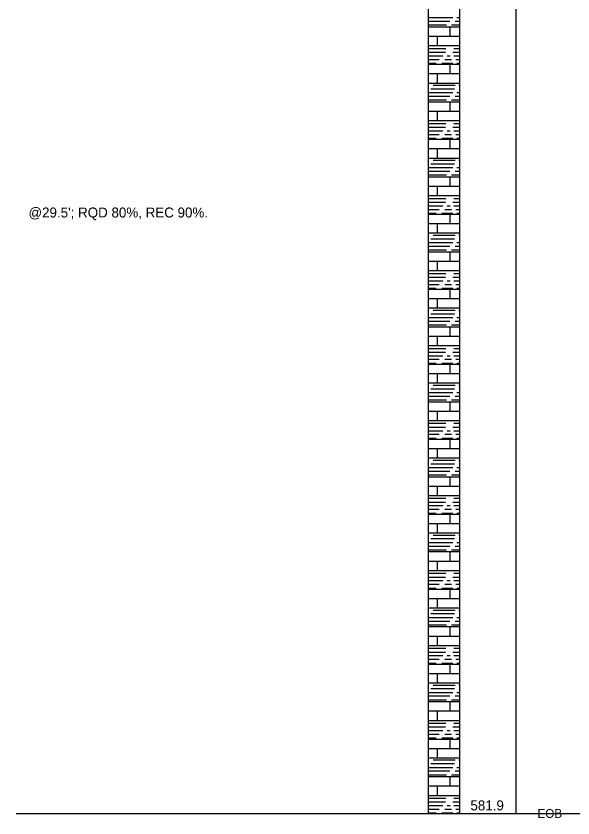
# Model space of a CAD drawing. Extents: x -0.01 to 0.83, y -0.63 to 1.27.
# Drawn here: x 0 to 0.372, y -0.625 to -0.09 of the extents above; entities that cross this region are included whole.
import ezdxf

# ---------------------------------------------------------------- set-up
doc = ezdxf.new("R2010")
doc.units = 0

msp = doc.modelspace()

# ---------------------------------------------------------------- linework, layer by layer
for points in [[(0.29583, 1.22083), (0.29583, -0.62183)], [(0.29583, 1.22083), (0.29583, -0.62183)], [(0.33333, 1.22083), (0.33333, -0.62183)], [(0.33333, 1.22083), (0.33333, -0.62183)], [(0.275, 1.19583), (0.275, -0.62183)], [(0.275, 0.21525), (0.275, -0.62183)], [(0.275, -0.09108), (0.29133, -0.09108)], [(0.275, -0.0935), (0.28933, -0.0935)], [(0.275, -0.096), (0.28725, -0.096)], [(0.2905, -0.096), (0.29583, -0.096)], [(0.293, -0.0935), (0.29583, -0.0935)], [(0.29417, -0.09108), (0.29583, -0.09108)], [(0.275, -0.09725), (0.29583, -0.09725)], [(0.28958, -0.1035), (0.28958, -0.09725)], [(0.275, -0.1035), (0.29583, -0.1035)], [(0.28125, -0.10975), (0.28125, -0.1035)], [(0.275, -0.10975), (0.29583, -0.10975)], [(0.275, -0.11167), (0.28683, -0.11167)], [(0.29217, -0.11167), (0.29583, -0.11167)], [(0.275, -0.11417), (0.28642, -0.11417)], [(0.275, -0.11658), (0.28483, -0.11658)], [(0.28767, -0.11658), (0.28967, -0.11658)], [(0.29133, -0.11417), (0.29583, -0.11417)], [(0.29217, -0.11658), (0.29583, -0.11658)], [(0.275, -0.119), (0.28233, -0.119)], [(0.275, -0.1215), (0.28033, -0.1215)], [(0.275, -0.12225), (0.29583, -0.12225)], [(0.284, -0.1215), (0.29133, -0.1215)], [(0.286, -0.119), (0.2905, -0.119)], [(0.28958, -0.1285), (0.28958, -0.12225)], [(0.29342, -0.119), (0.29583, -0.119)], [(0.29417, -0.1215), (0.29583, -0.1215)], [(0.275, -0.1285), (0.29583, -0.1285)], [(0.28125, -0.13475), (0.28125, -0.1285)], [(0.275, -0.13475), (0.29583, -0.13475)], [(0.27667, -0.13858), (0.29258, -0.13858)], [(0.27825, -0.13617), (0.293, -0.13617)], [(0.29542, -0.13617), (0.29583, -0.13617)], [(0.275, -0.14108), (0.29133, -0.14108)], [(0.275, -0.1435), (0.28933, -0.1435)], [(0.293, -0.1435), (0.29583, -0.1435)], [(0.29417, -0.14108), (0.29583, -0.14108)], [(0.275, -0.146), (0.28725, -0.146)], [(0.275, -0.14725), (0.29583, -0.14725)], [(0.28958, -0.1535), (0.28958, -0.14725)], [(0.2905, -0.146), (0.29583, -0.146)], [(0.275, -0.1535), (0.29583, -0.1535)], [(0.28125, -0.15975), (0.28125, -0.1535)], [(0.275, -0.15975), (0.29583, -0.15975)], [(0.275, -0.16167), (0.28683, -0.16167)], [(0.275, -0.16417), (0.28642, -0.16417)], [(0.29133, -0.16417), (0.29583, -0.16417)], [(0.29217, -0.16167), (0.29583, -0.16167)], [(0.275, -0.16658), (0.28483, -0.16658)], [(0.275, -0.169), (0.28233, -0.169)], [(0.286, -0.169), (0.2905, -0.169)], [(0.28767, -0.16658), (0.28967, -0.16658)], [(0.29217, -0.16658), (0.29583, -0.16658)], [(0.29342, -0.169), (0.29583, -0.169)], [(0.275, -0.1715), (0.28033, -0.1715)], [(0.275, -0.17225), (0.29583, -0.17225)], [(0.284, -0.1715), (0.29133, -0.1715)], [(0.28958, -0.1785), (0.28958, -0.17225)], [(0.29417, -0.1715), (0.29583, -0.1715)], [(0.275, -0.1785), (0.29583, -0.1785)], [(0.28125, -0.18475), (0.28125, -0.1785)], [(0.275, -0.18475), (0.29583, -0.18475)], [(0.27825, -0.18617), (0.293, -0.18617)], [(0.29542, -0.18617), (0.29583, -0.18617)], [(0.275, -0.19108), (0.29133, -0.19108)], [(0.27667, -0.18858), (0.29258, -0.18858)], [(0.29417, -0.19108), (0.29583, -0.19108)], [(0.275, -0.1935), (0.28933, -0.1935)], [(0.275, -0.196), (0.28725, -0.196)], [(0.275, -0.19725), (0.29583, -0.19725)], [(0.28958, -0.2035), (0.28958, -0.19725)], [(0.2905, -0.196), (0.29583, -0.196)], [(0.293, -0.1935), (0.29583, -0.1935)], [(0.275, -0.2035), (0.29583, -0.2035)], [(0.28125, -0.20975), (0.28125, -0.2035)], [(0.275, -0.20975), (0.29583, -0.20975)], [(0.275, -0.21167), (0.28683, -0.21167)], [(0.29217, -0.21167), (0.29583, -0.21167)], [(0.275, -0.21417), (0.28642, -0.21417)], [(0.275, -0.21658), (0.28483, -0.21658)], [(0.275, -0.219), (0.28233, -0.219)], [(0.286, -0.219), (0.2905, -0.219)], [(0.28767, -0.21658), (0.28967, -0.21658)], [(0.29133, -0.21417), (0.29583, -0.21417)], [(0.29217, -0.21658), (0.29583, -0.21658)], [(0.29342, -0.219), (0.29583, -0.219)], [(0.275, -0.2215), (0.28033, -0.2215)], [(0.275, -0.22225), (0.29583, -0.22225)], [(0.284, -0.2215), (0.29133, -0.2215)], [(0.28958, -0.2285), (0.28958, -0.22225)], [(0.29417, -0.2215), (0.29583, -0.2215)], [(0.275, -0.2285), (0.29583, -0.2285)], [(0.28125, -0.23475), (0.28125, -0.2285)], [(0.275, -0.23475), (0.29583, -0.23475)], [(0.27667, -0.23858), (0.29258, -0.23858)], [(0.27825, -0.23617), (0.293, -0.23617)], [(0.29542, -0.23617), (0.29583, -0.23617)], [(0.275, -0.24108), (0.29133, -0.24108)], [(0.275, -0.2435), (0.28933, -0.2435)], [(0.293, -0.2435), (0.29583, -0.2435)], [(0.29417, -0.24108), (0.29583, -0.24108)], [(0.275, -0.246), (0.28725, -0.246)], [(0.275, -0.24725), (0.29583, -0.24725)], [(0.28958, -0.2535), (0.28958, -0.24725)], [(0.2905, -0.246), (0.29583, -0.246)], [(0.275, -0.2535), (0.29583, -0.2535)], [(0.28125, -0.25975), (0.28125, -0.2535)], [(0.275, -0.25975), (0.29583, -0.25975)], [(0.275, -0.26167), (0.28683, -0.26167)], [(0.29217, -0.26167), (0.29583, -0.26167)], [(0.275, -0.26417), (0.28642, -0.26417)], [(0.275, -0.26658), (0.28483, -0.26658)], [(0.28767, -0.26658), (0.28967, -0.26658)], [(0.29133, -0.26417), (0.29583, -0.26417)], [(0.29217, -0.26658), (0.29583, -0.26658)], [(0.275, -0.269), (0.28233, -0.269)], [(0.275, -0.2715), (0.28033, -0.2715)], [(0.275, -0.27225), (0.29583, -0.27225)], [(0.284, -0.2715), (0.29133, -0.2715)], [(0.286, -0.269), (0.2905, -0.269)], [(0.28958, -0.2785), (0.28958, -0.27225)], [(0.29342, -0.269), (0.29583, -0.269)], [(0.29417, -0.2715), (0.29583, -0.2715)], [(0.275, -0.2785), (0.29583, -0.2785)], [(0.28125, -0.28475), (0.28125, -0.2785)], [(0.275, -0.28475), (0.29583, -0.28475)], [(0.27667, -0.28858), (0.29258, -0.28858)], [(0.27825, -0.28617), (0.293, -0.28617)], [(0.29542, -0.28617), (0.29583, -0.28617)], [(0.275, -0.29108), (0.29133, -0.29108)], [(0.275, -0.2935), (0.28933, -0.2935)], [(0.293, -0.2935), (0.29583, -0.2935)], [(0.29417, -0.29108), (0.29583, -0.29108)], [(0.275, -0.296), (0.28725, -0.296)], [(0.275, -0.29725), (0.29583, -0.29725)], [(0.28958, -0.3035), (0.28958, -0.29725)], [(0.2905, -0.296), (0.29583, -0.296)], [(0.275, -0.3035), (0.29583, -0.3035)], [(0.28125, -0.30975), (0.28125, -0.3035)], [(0.275, -0.30975), (0.29583, -0.30975)], [(0.275, -0.31167), (0.28683, -0.31167)], [(0.275, -0.31417), (0.28642, -0.31417)], [(0.29133, -0.31417), (0.29583, -0.31417)], [(0.29217, -0.31167), (0.29583, -0.31167)], [(0.275, -0.31658), (0.28483, -0.31658)], [(0.275, -0.319), (0.28233, -0.319)], [(0.286, -0.319), (0.2905, -0.319)], [(0.28767, -0.31658), (0.28967, -0.31658)], [(0.29217, -0.31658), (0.29583, -0.31658)], [(0.29342, -0.319), (0.29583, -0.319)], [(0.275, -0.3215), (0.28033, -0.3215)], [(0.275, -0.32225), (0.29583, -0.32225)], [(0.284, -0.3215), (0.29133, -0.3215)], [(0.28958, -0.3285), (0.28958, -0.32225)], [(0.29417, -0.3215), (0.29583, -0.3215)], [(0.275, -0.3285), (0.29583, -0.3285)], [(0.28125, -0.33475), (0.28125, -0.3285)], [(0.275, -0.33475), (0.29583, -0.33475)], [(0.27825, -0.33617), (0.293, -0.33617)], [(0.29542, -0.33617), (0.29583, -0.33617)], [(0.275, -0.34108), (0.29133, -0.34108)], [(0.27667, -0.33858), (0.29258, -0.33858)], [(0.29417, -0.34108), (0.29583, -0.34108)], [(0.275, -0.3435), (0.28933, -0.3435)], [(0.275, -0.346), (0.28725, -0.346)], [(0.275, -0.34725), (0.29583, -0.34725)], [(0.28958, -0.3535), (0.28958, -0.34725)], [(0.2905, -0.346), (0.29583, -0.346)], [(0.293, -0.3435), (0.29583, -0.3435)], [(0.275, -0.3535), (0.29583, -0.3535)], [(0.28125, -0.35975), (0.28125, -0.3535)], [(0.275, -0.35975), (0.29583, -0.35975)], [(0.275, -0.36167), (0.28683, -0.36167)], [(0.29217, -0.36167), (0.29583, -0.36167)], [(0.275, -0.36417), (0.28642, -0.36417)], [(0.275, -0.36658), (0.28483, -0.36658)], [(0.28767, -0.36658), (0.28967, -0.36658)], [(0.29133, -0.36417), (0.29583, -0.36417)], [(0.29217, -0.36658), (0.29583, -0.36658)], [(0.275, -0.369), (0.28233, -0.369)], [(0.275, -0.3715), (0.28033, -0.3715)], [(0.275, -0.37225), (0.29583, -0.37225)], [(0.284, -0.3715), (0.29133, -0.3715)], [(0.286, -0.369), (0.2905, -0.369)], [(0.28958, -0.3785), (0.28958, -0.37225)], [(0.29342, -0.369), (0.29583, -0.369)], [(0.29417, -0.3715), (0.29583, -0.3715)], [(0.275, -0.3785), (0.29583, -0.3785)], [(0.28125, -0.38475), (0.28125, -0.3785)], [(0.275, -0.38475), (0.29583, -0.38475)], [(0.27667, -0.38858), (0.29258, -0.38858)], [(0.27825, -0.38617), (0.293, -0.38617)], [(0.29542, -0.38617), (0.29583, -0.38617)], [(0.275, -0.39108), (0.29133, -0.39108)], [(0.275, -0.3935), (0.28933, -0.3935)], [(0.293, -0.3935), (0.29583, -0.3935)], [(0.29417, -0.39108), (0.29583, -0.39108)], [(0.275, -0.396), (0.28725, -0.396)], [(0.275, -0.39725), (0.29583, -0.39725)], [(0.28958, -0.4035), (0.28958, -0.39725)], [(0.2905, -0.396), (0.29583, -0.396)], [(0.275, -0.4035), (0.29583, -0.4035)], [(0.28125, -0.40975), (0.28125, -0.4035)], [(0.275, -0.40975), (0.29583, -0.40975)], [(0.275, -0.41167), (0.28683, -0.41167)], [(0.29217, -0.41167), (0.29583, -0.41167)], [(0.275, -0.41417), (0.28642, -0.41417)], [(0.275, -0.41658), (0.28483, -0.41658)], [(0.28767, -0.41658), (0.28967, -0.41658)], [(0.29133, -0.41417), (0.29583, -0.41417)], [(0.29217, -0.41658), (0.29583, -0.41658)], [(0.275, -0.419), (0.28233, -0.419)], [(0.275, -0.4215), (0.28033, -0.4215)], [(0.275, -0.42225), (0.29583, -0.42225)], [(0.284, -0.4215), (0.29133, -0.4215)], [(0.286, -0.419), (0.2905, -0.419)], [(0.28958, -0.4285), (0.28958, -0.42225)], [(0.29342, -0.419), (0.29583, -0.419)], [(0.29417, -0.4215), (0.29583, -0.4215)], [(0.275, -0.4285), (0.29583, -0.4285)], [(0.28125, -0.43475), (0.28125, -0.4285)], [(0.275, -0.43475), (0.29583, -0.43475)], [(0.27825, -0.43617), (0.293, -0.43617)], [(0.29542, -0.43617), (0.29583, -0.43617)], [(0.275, -0.44108), (0.29133, -0.44108)], [(0.275, -0.4435), (0.28933, -0.4435)], [(0.27667, -0.43858), (0.29258, -0.43858)], [(0.293, -0.4435), (0.29583, -0.4435)], [(0.29417, -0.44108), (0.29583, -0.44108)], [(0.275, -0.446), (0.28725, -0.446)], [(0.275, -0.44725), (0.29583, -0.44725)], [(0.28958, -0.4535), (0.28958, -0.44725)], [(0.2905, -0.446), (0.29583, -0.446)], [(0.275, -0.4535), (0.29583, -0.4535)], [(0.28125, -0.45975), (0.28125, -0.4535)], [(0.275, -0.45975), (0.29583, -0.45975)], [(0.275, -0.46167), (0.28683, -0.46167)], [(0.275, -0.46417), (0.28642, -0.46417)], [(0.29133, -0.46417), (0.29583, -0.46417)], [(0.29217, -0.46167), (0.29583, -0.46167)], [(0.275, -0.46658), (0.28483, -0.46658)], [(0.275, -0.469), (0.28233, -0.469)], [(0.286, -0.469), (0.2905, -0.469)], [(0.28767, -0.46658), (0.28967, -0.46658)], [(0.29217, -0.46658), (0.29583, -0.46658)], [(0.29342, -0.469), (0.29583, -0.469)], [(0.275, -0.4715), (0.28033, -0.4715)], [(0.275, -0.47225), (0.29583, -0.47225)], [(0.284, -0.4715), (0.29133, -0.4715)], [(0.28958, -0.4785), (0.28958, -0.47225)], [(0.29417, -0.4715), (0.29583, -0.4715)], [(0.275, -0.4785), (0.29583, -0.4785)], [(0.28125, -0.48475), (0.28125, -0.4785)], [(0.275, -0.48475), (0.29583, -0.48475)], [(0.27825, -0.48617), (0.293, -0.48617)], [(0.29542, -0.48617), (0.29583, -0.48617)], [(0.275, -0.49108), (0.29133, -0.49108)], [(0.27667, -0.48858), (0.29258, -0.48858)], [(0.29417, -0.49108), (0.29583, -0.49108)], [(0.275, -0.4935), (0.28933, -0.4935)], [(0.275, -0.496), (0.28725, -0.496)], [(0.275, -0.49725), (0.29583, -0.49725)], [(0.28958, -0.5035), (0.28958, -0.49725)], [(0.2905, -0.496), (0.29583, -0.496)], [(0.293, -0.4935), (0.29583, -0.4935)], [(0.275, -0.5035), (0.29583, -0.5035)], [(0.28125, -0.50975), (0.28125, -0.5035)], [(0.275, -0.50975), (0.29583, -0.50975)], [(0.275, -0.51167), (0.28683, -0.51167)], [(0.29217, -0.51167), (0.29583, -0.51167)], [(0.275, -0.51417), (0.28642, -0.51417)], [(0.275, -0.51658), (0.28483, -0.51658)], [(0.28767, -0.51658), (0.28967, -0.51658)], [(0.29133, -0.51417), (0.29583, -0.51417)], [(0.29217, -0.51658), (0.29583, -0.51658)], [(0.275, -0.519), (0.28233, -0.519)], [(0.275, -0.5215), (0.28033, -0.5215)], [(0.275, -0.52225), (0.29583, -0.52225)], [(0.284, -0.5215), (0.29133, -0.5215)], [(0.286, -0.519), (0.2905, -0.519)], [(0.28958, -0.5285), (0.28958, -0.52225)], [(0.29342, -0.519), (0.29583, -0.519)], [(0.29417, -0.5215), (0.29583, -0.5215)], [(0.275, -0.5285), (0.29583, -0.5285)], [(0.28125, -0.53475), (0.28125, -0.5285)], [(0.275, -0.53475), (0.29583, -0.53475)], [(0.27667, -0.53858), (0.29258, -0.53858)], [(0.27825, -0.53617), (0.293, -0.53617)], [(0.29542, -0.53617), (0.29583, -0.53617)], [(0.275, -0.54108), (0.29133, -0.54108)], [(0.275, -0.5435), (0.28933, -0.5435)], [(0.293, -0.5435), (0.29583, -0.5435)], [(0.29417, -0.54108), (0.29583, -0.54108)], [(0.275, -0.546), (0.28725, -0.546)], [(0.275, -0.54725), (0.29583, -0.54725)], [(0.28958, -0.5535), (0.28958, -0.54725)], [(0.2905, -0.546), (0.29583, -0.546)], [(0.275, -0.5535), (0.29583, -0.5535)], [(0.28125, -0.55975), (0.28125, -0.5535)], [(0.275, -0.55975), (0.29583, -0.55975)], [(0.275, -0.56167), (0.28683, -0.56167)], [(0.275, -0.56417), (0.28642, -0.56417)], [(0.275, -0.56658), (0.28483, -0.56658)], [(0.28767, -0.56658), (0.28967, -0.56658)], [(0.29133, -0.56417), (0.29583, -0.56417)], [(0.29217, -0.56167), (0.29583, -0.56167)], [(0.29217, -0.56658), (0.29583, -0.56658)], [(0.275, -0.569), (0.28233, -0.569)], [(0.275, -0.5715), (0.28033, -0.5715)], [(0.284, -0.5715), (0.29133, -0.5715)], [(0.286, -0.569), (0.2905, -0.569)], [(0.29342, -0.569), (0.29583, -0.569)], [(0.29417, -0.5715), (0.29583, -0.5715)], [(0.275, -0.57225), (0.29583, -0.57225)], [(0.28958, -0.5785), (0.28958, -0.57225)], [(0.275, -0.5785), (0.29583, -0.5785)], [(0.28125, -0.58475), (0.28125, -0.5785)], [(0.275, -0.58475), (0.29583, -0.58475)], [(0.27825, -0.58617), (0.293, -0.58617)], [(0.29542, -0.58617), (0.29583, -0.58617)], [(0.275, -0.59108), (0.29133, -0.59108)], [(0.275, -0.5935), (0.28933, -0.5935)], [(0.27667, -0.58858), (0.29258, -0.58858)], [(0.293, -0.5935), (0.29583, -0.5935)], [(0.29417, -0.59108), (0.29583, -0.59108)], [(0.275, -0.596), (0.28725, -0.596)], [(0.275, -0.59725), (0.29583, -0.59725)], [(0.28958, -0.6035), (0.28958, -0.59725)], [(0.2905, -0.596), (0.29583, -0.596)], [(0.275, -0.6035), (0.29583, -0.6035)], [(0.28125, -0.60975), (0.28125, -0.6035)], [(0.275, -0.60975), (0.29583, -0.60975)], [(0.275, -0.61167), (0.28683, -0.61167)], [(0.275, -0.61417), (0.28642, -0.61417)], [(0.29133, -0.61417), (0.29583, -0.61417)], [(0.29217, -0.61167), (0.29583, -0.61167)], [(0.275, -0.61658), (0.28483, -0.61658)], [(0.275, -0.619), (0.28233, -0.619)], [(0.286, -0.619), (0.2905, -0.619)], [(0.28767, -0.61658), (0.28967, -0.61658)], [(0.29217, -0.61658), (0.29583, -0.61658)], [(0.29342, -0.619), (0.29583, -0.619)], [(0, -0.62183), (0.275, -0.62183)], [(0.275, -0.6215), (0.28033, -0.6215)], [(0.275, -0.62183), (0.29583, -0.62183)], [(0.275, -0.62183), (0.29583, -0.62183)], [(0.284, -0.6215), (0.29133, -0.6215)], [(0.29417, -0.6215), (0.29583, -0.6215)], [(0.29583, -0.62183), (0.33333, -0.62183)], [(0.33333, -0.62183), (0.37917, -0.62183)]]:
    msp.add_lwpolyline(points)

# ---------------------------------------------------------------- texts
for s, height, p in [("@29.5'; RQD 80%, REC 90%.", 0.0066667, (0.00833, -0.22442)), ('581.9', 0.006667, (0.30314, -0.61979)), ('EOB', 0.005833, (0.34786, -0.62475))]:
    msp.add_text(s, height=height).set_placement(p)

doc.saveas('drawing.dxf')
